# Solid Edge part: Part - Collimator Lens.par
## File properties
Author: hhakima
Template: Normal.par
Last saved by: hhakima
Revision: 6
Application: Solid Edge
Accuracy: 0.990
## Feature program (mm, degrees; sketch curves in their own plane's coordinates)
sketch for "unnamed Protrusion 1" plane through (0, 0, 0) normal (0, 0, 1) x-axis (1, 0, 0)
  circle centre (0, 0) radius 4.5
extrude "unnamed Protrusion 1" add finite 2 along -normal
fillet "Round_1" radius 2
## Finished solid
Body 1: solid body, 3 faces, 2 edges, 0 vertices.
  Faces by surface: plane 2, torus 1
  Edges by curve: circle 2
Bounding box of the edges (mm; curved faces can reach further): 9.000 x 9.000 x 2.000, from (-4.5, -4.5, -2) to (4.5, 4.5, 0).
Toroidal faces (ring radius, tube radius in mm): R2.5 r2 x1
Planar faces by outward normal: +z 1, -z 1
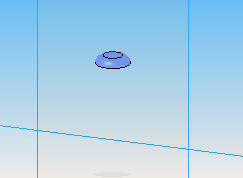
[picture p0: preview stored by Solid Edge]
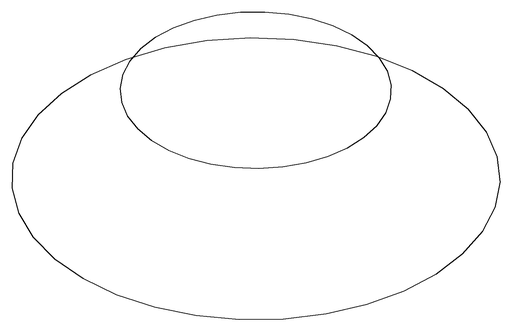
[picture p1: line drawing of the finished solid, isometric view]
